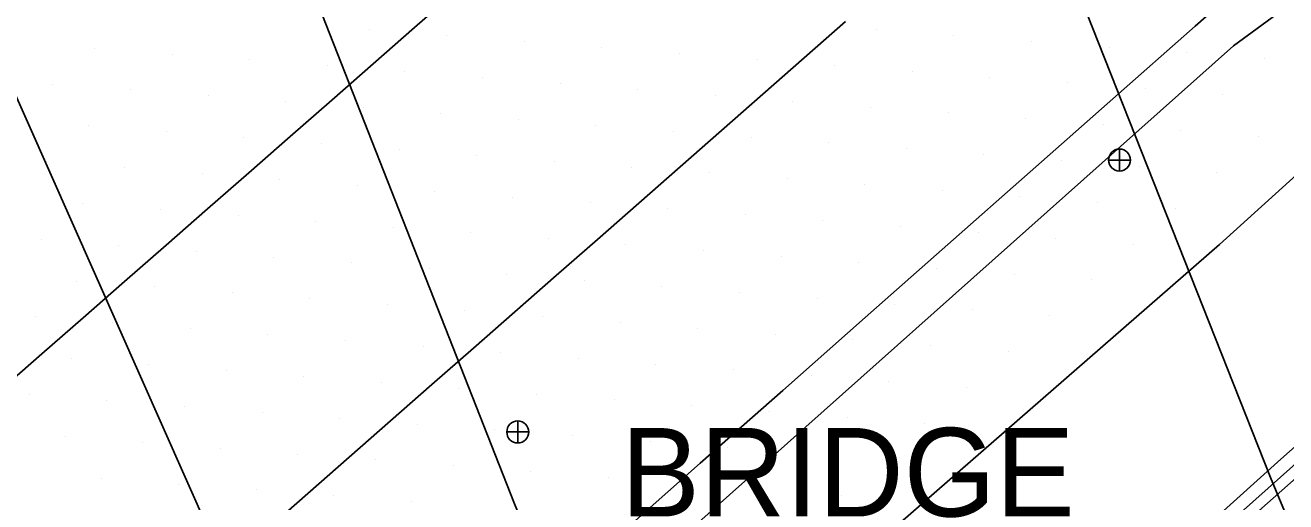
# Model space of a CAD drawing. Extents: x 1548934 to 1561348, y 809680 to 824075.
# Drawn here: x 1551783.3 to 1551840.5, y 810743.4 to 810765.1 of the extents above; entities that cross this region are included whole.
import ezdxf

# ---------------------------------------------------------------- set-up
doc = ezdxf.new("R2010")
doc.units = 0
for name, color, linetype in [('Default', 7, 'Continuous'), ('E_NCDOT_Vertical_Profile_Ground_Line', 7, 'Continuous'), ('Exist DTM Scan Elevation Point', 7, 'Continuous'), ('Exist Structure Major Bridge Seam Top Elevation', 7, 'Continuous'), ('Exist Structure Major Deck Tunnel Box Culvert', 7, 'Continuous'), ('P_RDY_Terminator_Cell', 7, 'Continuous'), ('Pattern_8', 7, 'Continuous'), ('PH Exist DTM Breakline', 7, 'Continuous')]:
    doc.layers.add(name, color=color, linetype=linetype)

# ---------------------------------------------------------------- blocks, each defined once
blk = doc.blocks.new('SurveyPointCell')
at = {"layer": 'Default'}
for p, q in [((-0.5, 0), (0.5, 0)), ((0, -0.5), (0, 0.5))]:
    blk.add_line(p, q, dxfattribs=at)
blk.add_circle((0, 0), 0.5, dxfattribs=at)

msp = doc.modelspace()

# ---------------------------------------------------------------- linework, layer by layer
at = {"layer": 'E_NCDOT_Vertical_Profile_Ground_Line'}
msp.add_lwpolyline([(1551730.822, 810673.853), (1551753.618, 810693.379), (1551776.873, 810712.355), (1551777.906, 810712.877), (1551778.938, 810713.401), (1551779.968, 810713.927), (1551780.996, 810714.457), (1551782.03, 810714.977), (1551783.082, 810715.455), (1551784.165, 810715.86), (1551785.276, 810716.172), (1551786.405, 810716.412), (1551787.541, 810716.606), (1551788.679, 810716.776), (1551789.821, 810716.924), (1551790.968, 810717.039), (1551792.121, 810717.111), (1551793.277, 810717.148), (1551803.243, 810725.955), (1551814.903, 810735.412), (1551826.218, 810745.259), (1551837.521, 810755.119), (1551848.5, 810765.046)], dxfattribs=at)
at = {"layer": 'Exist DTM Scan Elevation Point'}
for p, q in [((1551798.888, 810764.859), (1551798.888, 810764.859)), ((1551821.935, 810764.882), (1551821.935, 810764.882)), ((1551802.413, 810764.591), (1551802.413, 810764.591)), ((1551805.938, 810764.324), (1551805.938, 810764.324)), ((1551825.461, 810764.615), (1551825.461, 810764.615)), ((1551828.987, 810764.348), (1551828.987, 810764.348)), ((1551786.416, 810764.033), (1551786.416, 810764.033)), ((1551789.941, 810763.765), (1551789.941, 810763.765)), ((1551809.463, 810764.056), (1551809.463, 810764.056)), ((1551812.988, 810763.788), (1551812.988, 810763.788)), ((1551832.513, 810764.081), (1551832.513, 810764.081)), ((1551836.04, 810763.815), (1551836.04, 810763.815)), ((1551793.466, 810763.498), (1551793.466, 810763.498)), ((1551796.991, 810763.23), (1551796.991, 810763.23)), ((1551816.513, 810763.521), (1551816.513, 810763.521)), ((1551820.039, 810763.253), (1551820.039, 810763.253)), ((1551839.567, 810763.549), (1551839.567, 810763.549)), ((1551800.516, 810762.963), (1551800.516, 810762.963)), ((1551804.041, 810762.695), (1551804.041, 810762.695)), ((1551823.565, 810762.986), (1551823.565, 810762.986)), ((1551827.091, 810762.719), (1551827.091, 810762.719)), ((1551830.617, 810762.452), (1551830.617, 810762.452)), ((1551784.519, 810762.404), (1551784.519, 810762.404)), ((1551788.044, 810762.137), (1551788.044, 810762.137)), ((1551791.57, 810761.869), (1551791.57, 810761.869)), ((1551807.566, 810762.427), (1551807.566, 810762.427)), ((1551811.092, 810762.159), (1551811.092, 810762.159)), ((1551814.617, 810761.892), (1551814.617, 810761.892)), ((1551834.143, 810762.186), (1551834.143, 810762.186)), ((1551837.671, 810761.92), (1551837.671, 810761.92)), ((1551795.095, 810761.601), (1551795.095, 810761.601)), ((1551798.62, 810761.334), (1551798.62, 810761.334)), ((1551818.142, 810761.624), (1551818.142, 810761.624)), ((1551821.668, 810761.357), (1551821.668, 810761.357)), ((1551802.145, 810761.066), (1551802.145, 810761.066)), ((1551805.67, 810760.798), (1551805.67, 810760.798)), ((1551825.194, 810761.09), (1551825.194, 810761.09)), ((1551828.72, 810760.823), (1551828.72, 810760.823)), ((1551786.148, 810760.508), (1551786.148, 810760.508)), ((1551789.673, 810760.24), (1551789.673, 810760.24)), ((1551809.195, 810760.53), (1551809.195, 810760.53)), ((1551812.721, 810760.263), (1551812.721, 810760.263)), ((1551832.247, 810760.557), (1551832.247, 810760.557)), ((1551835.774, 810760.291), (1551835.774, 810760.291)), ((1551793.198, 810759.972), (1551793.198, 810759.972)), ((1551796.724, 810759.705), (1551796.724, 810759.705)), ((1551816.246, 810759.995), (1551816.246, 810759.995)), ((1551819.772, 810759.728), (1551819.772, 810759.728)), ((1551839.302, 810760.026), (1551839.302, 810760.026)), ((1551800.249, 810759.437), (1551800.249, 810759.437)), ((1551803.774, 810759.169), (1551803.774, 810759.169)), ((1551823.298, 810759.461), (1551823.298, 810759.461)), ((1551826.824, 810759.194), (1551826.824, 810759.194)), ((1551784.252, 810758.879), (1551784.252, 810758.879)), ((1551787.777, 810758.611), (1551787.777, 810758.611)), ((1551807.299, 810758.901), (1551807.299, 810758.901)), ((1551810.824, 810758.634), (1551810.824, 810758.634)), ((1551830.35, 810758.928), (1551830.35, 810758.928)), ((1551833.878, 810758.662), (1551833.878, 810758.662)), ((1551791.302, 810758.343), (1551791.302, 810758.343)), ((1551794.827, 810758.076), (1551794.827, 810758.076)), ((1551814.35, 810758.367), (1551814.35, 810758.367)), ((1551817.875, 810758.099), (1551817.875, 810758.099)), ((1551837.405, 810758.397), (1551837.405, 810758.397)), ((1551798.352, 810757.808), (1551798.352, 810757.808)), ((1551801.877, 810757.54), (1551801.877, 810757.54)), ((1551821.401, 810757.832), (1551821.401, 810757.832)), ((1551824.928, 810757.566), (1551824.928, 810757.566)), ((1551828.454, 810757.299), (1551828.454, 810757.299)), ((1551785.881, 810756.982), (1551785.881, 810756.982)), ((1551789.406, 810756.715), (1551789.406, 810756.715)), ((1551805.402, 810757.273), (1551805.402, 810757.273)), ((1551808.928, 810757.005), (1551808.928, 810757.005)), ((1551812.453, 810756.738), (1551812.453, 810756.738)), ((1551831.981, 810757.033), (1551831.981, 810757.033)), ((1551835.509, 810756.768), (1551835.509, 810756.768)), ((1551792.931, 810756.447), (1551792.931, 810756.447)), ((1551796.456, 810756.179), (1551796.456, 810756.179)), ((1551815.979, 810756.471), (1551815.979, 810756.471)), ((1551819.505, 810756.204), (1551819.505, 810756.204)), ((1551799.981, 810755.911), (1551799.981, 810755.911)), ((1551803.506, 810755.644), (1551803.506, 810755.644)), ((1551823.031, 810755.937), (1551823.031, 810755.937)), ((1551826.558, 810755.67), (1551826.558, 810755.67)), ((1551783.984, 810755.353), (1551783.984, 810755.353)), ((1551787.509, 810755.086), (1551787.509, 810755.086)), ((1551807.031, 810755.376), (1551807.031, 810755.376)), ((1551810.557, 810755.109), (1551810.557, 810755.109)), ((1551830.085, 810755.404), (1551830.085, 810755.404)), ((1551833.613, 810755.139), (1551833.613, 810755.139)), ((1551791.034, 810754.818), (1551791.034, 810754.818)), ((1551794.56, 810754.55), (1551794.56, 810754.55)), ((1551814.083, 810754.842), (1551814.083, 810754.842)), ((1551817.609, 810754.575), (1551817.609, 810754.575)), ((1551798.085, 810754.282), (1551798.085, 810754.282)), ((1551801.61, 810754.015), (1551801.61, 810754.015)), ((1551821.135, 810754.308), (1551821.135, 810754.308)), ((1551824.661, 810754.041), (1551824.661, 810754.041)), ((1551785.613, 810753.457), (1551785.613, 810753.457)), ((1551805.135, 810753.747), (1551805.135, 810753.747)), ((1551808.661, 810753.48), (1551808.661, 810753.48)), ((1551828.189, 810753.775), (1551828.189, 810753.775)), ((1551831.716, 810753.51), (1551831.716, 810753.51)), ((1551789.138, 810753.189), (1551789.138, 810753.189)), ((1551792.663, 810752.921), (1551792.663, 810752.921)), ((1551812.186, 810753.213), (1551812.186, 810753.213)), ((1551815.712, 810752.946), (1551815.712, 810752.946)), ((1551796.188, 810752.654), (1551796.188, 810752.654)), ((1551799.713, 810752.386), (1551799.713, 810752.386)), ((1551819.238, 810752.679), (1551819.238, 810752.679)), ((1551822.765, 810752.412), (1551822.765, 810752.412)), ((1551826.292, 810752.146), (1551826.292, 810752.146)), ((1551783.717, 810751.828), (1551783.717, 810751.828)), ((1551787.242, 810751.56), (1551787.242, 810751.56)), ((1551803.239, 810752.118), (1551803.239, 810752.118)), ((1551806.764, 810751.851), (1551806.764, 810751.851)), ((1551810.29, 810751.584), (1551810.29, 810751.584)), ((1551829.82, 810751.881), (1551829.82, 810751.881)), ((1551790.767, 810751.292), (1551790.767, 810751.292)), ((1551794.292, 810751.025), (1551794.292, 810751.025)), ((1551813.816, 810751.317), (1551813.816, 810751.317)), ((1551817.342, 810751.05), (1551817.342, 810751.05)), ((1551797.817, 810750.757), (1551797.817, 810750.757)), ((1551801.342, 810750.489), (1551801.342, 810750.489)), ((1551820.868, 810750.783), (1551820.868, 810750.783)), ((1551824.396, 810750.518), (1551824.396, 810750.518)), ((1551785.345, 810749.931), (1551785.345, 810749.931)), ((1551804.868, 810750.222), (1551804.868, 810750.222)), ((1551808.394, 810749.955), (1551808.394, 810749.955)), ((1551827.924, 810750.252), (1551827.924, 810750.252)), ((1551788.87, 810749.663), (1551788.87, 810749.663)), ((1551792.396, 810749.396), (1551792.396, 810749.396)), ((1551811.92, 810749.688), (1551811.92, 810749.688)), ((1551815.446, 810749.421), (1551815.446, 810749.421)), ((1551795.921, 810749.128), (1551795.921, 810749.128)), ((1551799.446, 810748.86), (1551799.446, 810748.86)), ((1551818.972, 810749.154), (1551818.972, 810749.154)), ((1551822.499, 810748.888), (1551822.499, 810748.888)), ((1551783.449, 810748.302), (1551783.449, 810748.302)), ((1551802.971, 810748.593), (1551802.971, 810748.593)), ((1551806.497, 810748.326), (1551806.497, 810748.326)), ((1551826.027, 810748.623), (1551826.027, 810748.623)), ((1551786.974, 810748.034), (1551786.974, 810748.034)), ((1551790.499, 810747.767), (1551790.499, 810747.767)), ((1551810.023, 810748.059), (1551810.023, 810748.059)), ((1551813.549, 810747.792), (1551813.549, 810747.792)), ((1551794.024, 810747.499), (1551794.024, 810747.499)), ((1551797.55, 810747.231), (1551797.55, 810747.231)), ((1551817.076, 810747.525), (1551817.076, 810747.525)), ((1551820.603, 810747.26), (1551820.603, 810747.26)), ((1551824.13, 810746.994), (1551824.13, 810746.994)), ((1551785.078, 810746.406), (1551785.078, 810746.406)), ((1551801.075, 810746.964), (1551801.075, 810746.964)), ((1551804.601, 810746.697), (1551804.601, 810746.697)), ((1551808.127, 810746.43), (1551808.127, 810746.43)), ((1551788.603, 810746.138), (1551788.603, 810746.138)), ((1551792.128, 810745.87), (1551792.128, 810745.87)), ((1551811.653, 810746.163), (1551811.653, 810746.163)), ((1551815.179, 810745.897), (1551815.179, 810745.897)), ((1551795.653, 810745.603), (1551795.653, 810745.603)), ((1551799.179, 810745.335), (1551799.179, 810745.335)), ((1551818.707, 810745.631), (1551818.707, 810745.631)), ((1551822.235, 810745.365), (1551822.235, 810745.365)), ((1551802.705, 810745.068), (1551802.705, 810745.068)), ((1551806.231, 810744.801), (1551806.231, 810744.801)), ((1551786.706, 810744.509), (1551786.706, 810744.509)), ((1551790.232, 810744.241), (1551790.232, 810744.241)), ((1551809.757, 810744.534), (1551809.757, 810744.534)), ((1551813.283, 810744.268), (1551813.283, 810744.268)), ((1551793.757, 810743.973), (1551793.757, 810743.973)), ((1551797.282, 810743.706), (1551797.282, 810743.706)), ((1551816.81, 810744.002), (1551816.81, 810744.002)), ((1551820.338, 810743.736), (1551820.338, 810743.736)), ((1551800.808, 810743.439), (1551800.808, 810743.439))]:
    msp.add_line(p, q, dxfattribs=at)
at = {"layer": 'Exist Structure Major Deck Tunnel Box Culvert'}
for points in [[(1551890.16, 810628.772), (1551869.489, 810674.52), (1551854.065, 810710.393), (1551839.842, 810744.541), (1551817.227, 810801.667), (1551801.118, 810844.761), (1551789.242, 810877.577)], [(1551763.353, 810854.68), (1551776.069, 810819.842), (1551783.152, 810800.687), (1551795.344, 810769.157), (1551805.495, 810743.337), (1551817.592, 810713.867), (1551830.145, 810684.596), (1551846.388, 810647.478), (1551862.114, 810612.886), (1551864.95, 810606.898)]]:
    msp.add_lwpolyline(points, dxfattribs=at)
at = {"layer": 'P_RDY_Terminator_Cell'}
for points in [[(1551854.512, 810780.962), (1551852.912, 810779.601), (1551849.914, 810776.954), (1551846.916, 810774.306), (1551840.17, 810768.349), (1551836.422, 810765.04), (1551832.674, 810761.73), (1551828.926, 810758.421), (1551825.178, 810755.111), (1551821.431, 810751.802), (1551817.683, 810748.492), (1551813.935, 810745.183), (1551810.187, 810741.873), (1551806.439, 810738.564), (1551802.692, 810735.254), (1551795.196, 810728.635), (1551791.448, 810725.326), (1551787.7, 810722.017), (1551783.953, 810718.707), (1551783.318, 810718.146)], [(1551802.822, 810766.623), (1551800.947, 810764.97), (1551799.069, 810763.319), (1551797.188, 810761.673), (1551795.307, 810760.026), (1551793.425, 810758.38), (1551791.544, 810756.733), (1551789.663, 810755.087), (1551787.781, 810753.441), (1551785.9, 810751.794), (1551784.019, 810750.148), (1551782.137, 810748.501)], [(1551820.539, 810765.242), (1551818.66, 810763.594), (1551816.78, 810761.945), (1551814.901, 810760.297), (1551813.021, 810758.648), (1551811.142, 810757), (1551809.262, 810755.352), (1551807.382, 810753.703), (1551805.503, 810752.055), (1551803.623, 810750.406), (1551801.744, 810748.758), (1551799.864, 810747.11), (1551797.985, 810745.461), (1551796.105, 810743.813), (1551794.226, 810742.164), (1551792.346, 810740.516), (1551790.463, 810738.872), (1551788.578, 810737.229), (1551786.694, 810735.586), (1551784.81, 810733.943), (1551782.925, 810732.3)], [(1551854.975, 810757.675), (1551843.796, 810747.674), (1551832.599, 810737.693), (1551821.511, 810727.588), (1551810.27, 810717.657), (1551799.168, 810707.769)], [(1551855.42, 810757.218), (1551844.155, 810747.31), (1551832.897, 810737.352), (1551821.785, 810727.271), (1551810.575, 810717.321), (1551799.474, 810707.426)]]:
    msp.add_lwpolyline(points, dxfattribs=at)
at = {"layer": 'Pattern_8'}
msp.add_lwpolyline([(1551772.004, 810786.253), (1551837.927, 810637.788)], dxfattribs=at)
at = {"layer": 'PH Exist DTM Breakline'}
for points in [[(1551852.685, 810774.381), (1551844.675, 810768.929), (1551838.155, 810764.144), (1551796.663, 810727.191), (1551785.488, 810716.232)], [(1551854.933, 810757.899), (1551846.117, 810750.504), (1551840.309, 810745.37), (1551811.437, 810719.348), (1551801.976, 810710.638), (1551798.234, 810708.524)]]:
    msp.add_lwpolyline(points, dxfattribs=at)

# ---------------------------------------------------------------- block references
at = {"layer": 'Default'}
for p in [(1551832.981, 810758.952), (1551805.642, 810746.605)]:
    msp.add_blockref('SurveyPointCell', p, dxfattribs=at)

# ---------------------------------------------------------------- texts
at = {"layer": 'Exist Structure Major Bridge Seam Top Elevation'}
msp.add_text('BRIDGE', height=4.02, dxfattribs=at).set_placement((1551810.331, 810742.767))

doc.saveas('drawing.dxf')
